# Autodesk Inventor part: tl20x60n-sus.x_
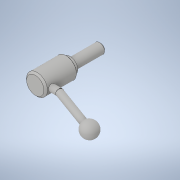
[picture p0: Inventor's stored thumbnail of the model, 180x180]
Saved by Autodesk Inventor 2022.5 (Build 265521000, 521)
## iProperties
Created: 2021-02
Part Number: tl20x60n-sus.x_
Material: 一般
Document SubType Name: Modeling
Designer: ImaoCorp
Density: 1 g/cm^3
Appearance: 既定
Sending System: SOLIDWORKS 2019-2019304
MC: AMD64
MC_MODEL: Intel64 Family 6 Model 60 Stepping 3, GenuineIntel
OS: Windows_NT
FRU: Parasolid Version 31.0, build 290,  9- 1-2019
FORMAT: text
GUISE: transmit
KEY: tl20x60n-sus
FILE: tl20x60n-sus.x_t
DATE: Mon Feb 22 14:52:01 2021
Author: ImaoCorp
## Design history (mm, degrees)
feature "Base1"
node "ソリッド1"
